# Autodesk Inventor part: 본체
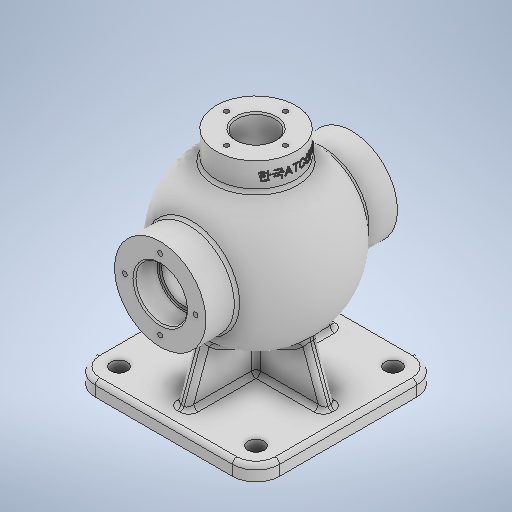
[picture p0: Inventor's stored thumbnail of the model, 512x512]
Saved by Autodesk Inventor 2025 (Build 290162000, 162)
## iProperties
Created: 2024-07
Part Number: 본체
Material: 일반
Document SubType Name: Modeling
Designer: parkm
Density: 1 g/cm^3
Appearance: 기본값
Author: parkm
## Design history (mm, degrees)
sketch "스케치1"
  geometry: L1 (62.5, 62.5)-(-62.5, 62.5); L2 (-62.5, 62.5)-(-62.5, -62.5); L3 (-62.5, -62.5)-(62.5, -62.5); L4 (62.5, -62.5)-(62.5, 62.5); L5 (62.5, 62.5)-(-62.5, -62.5); L6 (-62.5, 62.5)-(62.5, -62.5); 1 further point
  constraints: 12 end point, 2 midpoint, 2 parallel, 1 horizontal, 1 perpendicular
  dimensions: "d0" = 125 distance of L2.end L3.end; "d1" = 125 distance of L1.end L2.end
extrude "돌출1" new body sketch "스케치1" distance "d2" = 10; taper "d3" = 0 deg
fillet "모깎기1" dims "d4" = 16
sketch "스케치2"
  geometry: L1 (-46.5, 0)-(46.5, 0) reference; L2 (0, 144.733)-(0, 0); A1 r 54 centre (0, 85) between (0, 31) and (0, 139); 2 further points
  constraints: 2 end point, 2 midpoint, 2 point on circle, 2 point on line, 1 centre point, 1 vertical, 1 vertical alignment
  dimensions: "d5" = 108 diameter of A1; "d6" = 85 distance of L2.end A1.centre
revolve "회전1" sketch "스케치2" stored, may be unused: angle "d7" = 90 deg
sketch "스케치3"
  geometry: L1 (50, 35.941)-(10, 50.5); L2 (10, 62.5)-(10, 46.5) reference; L3 (0, 62.5)-(10, 62.5) reference; L4 (0, 0)-(175.833, 0); L5 (50, -35.941)-(10, -50.5); L6 (10, 50.5)-(10, -50.5); L7 (10, -46.5)-(10, 46.5) reference; L8 (10, -62.5)-(0, -62.5) reference; L9 (0, -62.5)-(10, -62.5) reference; A1 r 57.102 centre (94.372, 0) between (50, 35.941) and (71.299, -52.233); 7 further points
  constraints: 8 end point, 2 midpoint, 2 point on circle, 2 point on line, 2 symmetric about line, 1 centre point, 1 collinear, 1 equal length, 1 horizontal, 2 other
  dimensions: "d8" = 12 vertical distance of point (5, 62.5) L1.end; "d9" = 20 deg angle of L1 L3; "d13" = 20 deg angle of L5 L8; "d14" = 40 horizontal distance of L1.start L1.end; "d89" = 12 vertical distance of point (5, -62.5) L5.end (derived)
extrude "돌출2" join sketch "스케치3" stored distance "d11" = 8; taper "d12" = 0 deg
sketch "스케치4"
  geometry: L1 (-30.003, 66.314)-(-50.5, 10); L2 (30.003, 66.314)-(50.5, 10); L3 (-62.5, 10)-(-46.5, 10) reference; L4 (46.5, 10)-(62.5, 10) reference; L5 (-62.5, 0)-(-62.5, 10) reference; L6 (62.5, 10)-(62.5, 0) reference; L7 (-50.5, 10)-(50.5, 10); A1 r 46.287 centre (0, 101.56) between (-30.003, 66.314) and (30.003, 66.314); 3 further points
  constraints: 6 end point, 2 point on circle, 2 point on line, 1 centre point, 1 collinear, 1 equal length
  dimensions: "d15" = 12 distance from line of L1.end L5; "d16" = 12 distance from line of L2.end L6; "d17" = 20 deg angle of L1 L5; "d18" = 20 deg angle of L2 L6
extrude "돌출3" join sketch "스케치4" stored distance "d19" = 8; taper "d20" = 0 deg
fillet "모깎기2" dims "d21" = 3
fillet "모깎기3" dims "d22" = 3
fillet "모깎기4" dims "d23" = 3
fillet "모깎기5" dims "d24" = 3
sketch "스케치5"
  geometry: C1 r 31 at (0, 85); A1 r 54 centre (0, 85) between (38.709, 47.349) and (-38.709, 47.349) reference; 1 further point
  constraints: 1 centre point, 1 concentric
  dimensions: "d25" = 62 diameter of C1
extrude "돌출4" join sketch "스케치5" stored distance "d26" = 130; taper "d27" = 0 deg
fillet "모깎기6" dims "d28" = 3
node "작업 평면1"
sketch "스케치6"
  geometry: C1 r 27 at (0, 0); 1 further point
  constraints: 1 centre point, 1 coincident
  dimensions: "d30" = 54 diameter of C1
extrude "돌출5" join sketch "스케치6" distance "d31" = 30; taper "d32" = 0 deg
fillet "모깎기7" dims "d33" = 3
sketch "스케치8"
  geometry: L1 (0, 0)-(0, 160.102); A1 r 44 centre (0, 85) between (0, 41) and (0, 129); A2 r 54 centre (0, 85) between (38.709, 47.349) and (-38.709, 47.349) reference
  constraints: 2 end point, 2 point on circle, 2 point on line, 1 centre point, 1 concentric, 1 vertical
  dimensions: "d34" = 88 diameter of A1
revolve "회전2" sketch "스케치8" stored, may be unused: angle "d39" = 90 deg
sketch "스케치9"
  geometry: C1 r 31 at (0, 0) reference; C2 r 17.5 at (0, 0); 1 further point
  constraints: 1 centre point, 1 coincident
  dimensions: "d40" = 35 diameter of C2
extrude "돌출6" cut sketch "스케치9" distance "d41" = 16; taper "d42" = 0 deg
sketch "스케치10"
  geometry: C1 r 17.5 at (0, 0) reference; 1 further point
extrude "돌출7" cut sketch "스케치10" distance "d43" = 16; taper "d44" = 0 deg
sketch "스케치11"
  geometry: C1 r 17.5 at (0, 0) reference; C2 r 15 at (0, 0); 1 further point
  constraints: 1 centre point, 1 coincident
  dimensions: "d45" = 30 diameter of C2
extrude "돌출8" cut sketch "스케치11" extent not by distance; stored distance "d46" = 0; taper "d47" = 0 deg
sketch "스케치12"
  geometry: C1 r 13 at (0, 0); 1 further point
  constraints: 1 centre point, 1 coincident
  dimensions: "d48" = 26 diameter of C1
extrude "돌출9" cut sketch "스케치12" stored distance "d49" = 10; taper "d50" = 0 deg
chamfer "모따기1" distance "d51" = 1; stored, may be unused: second distance "d52" = 2, angle "d53" = 45 deg
fillet "모깎기8" dims "d54" = 0.6
sketch "스케치13"
  geometry: L1 (-70.97, 0)-(83.117, 0); L2 (0, 46.873)-(0, -34.996); C1 r 31 at (0, 0) reference; A1 r 24 centre (0, 0) between (0, 24) and (-24, 0); 3 further points
  constraints: 6 point on line, 4 end point, 4 point on circle, 1 centre point, 1 concentric, 1 horizontal, 1 vertical
  dimensions: "d55" = 48 diameter of A1
hole "구멍1" sketch "스케치13" at (0, 24), (-24, 0), (0, -24), (24, 0) diameter "d56" = 3.242; stored, may be unused: countersink angle "d60" = 90 deg, drill point angle "d62" = 120 deg; dims "d57" = 12, "d58" = 4, "d59" = 2, "d61" = 15
sketch "스케치14"
  geometry: C1 r 1.621 at (-24, 0) reference; C2 r 1.621 at (0, 24) reference; C3 r 1.621 at (24, 0) reference; C4 r 1.621 at (0, -24) reference; 1 further point
hole "구멍2" sketch "스케치14" at (0, 24), (-24, 0), (0, -24), (24, 0) diameter "d63" = 3.242; stored, may be unused: countersink angle "d67" = 90 deg, drill point angle "d69" = 120 deg; dims "d64" = 12, "d65" = 4, "d66" = 2, "d68" = 15
sketch "스케치15"
  geometry: L1 (-105.545, 0)-(92.862, 0); L2 (0, 73.134)-(0, -31.988); A1 r 20 centre (0, 0) between (0, 20) and (-20, 0); 3 further points
  constraints: 5 point on line, 4 end point, 4 point on circle, 1 centre point, 1 coincident, 1 horizontal, 1 vertical
  dimensions: "d70" = 40 diameter of A1
hole "구멍3" sketch "스케치15" at (0, 20), (-20, 0), (20, 0), (0, -20) diameter "d71" = 3.242; stored, may be unused: countersink angle "d75" = 90 deg, drill point angle "d77" = 120 deg; dims "d72" = 9, "d73" = 4, "d74" = 2, "d76" = 11
sketch "스케치16"
  geometry: A1 r 13 centre (46.5, -46.5) between (46.5, -59.5) and (59.5, -46.5) reference; A2 r 13 centre (46.5, 46.5) between (59.5, 46.5) and (46.5, 59.5) reference; A3 r 13 centre (-46.5, -46.5) between (-59.5, -46.5) and (-46.5, -59.5) reference; A4 r 13 centre (-46.5, 46.5) between (-46.5, 59.5) and (-59.5, 46.5) reference; 5 further points
  constraints: 4 coincident
hole "구멍4" sketch "스케치16" at (46.5, -46.5), (46.5, 46.5), (-46.5, -46.5), (-46.5, 46.5) diameter "d78" = 11; stored, may be unused: countersink angle "d82" = 90 deg, drill point angle "d84" = 0 deg; dims "d79" = 9, "d80" = 4, "d81" = 2, "d83" = 11
node "작업 평면2"
sketch "스케치17"
  geometry: L1 (150, -27)-(150, 27) reference; L2 (0, 0)-(196.455, 0); 1 further point
  constraints: 2 end point, 1 horizontal, 1 point on line, 1 other
  dimensions: "d86" = 9 distance from line of point (141, 0) L1
feature "엠보싱1" sketch "스케치17" dims "d0" = 125, "d1" = 125, "d87" = 0.5, "d88" = 0
node "솔리드1"
node "투영된 루프1"
feature "A9D066F2-1C7D-4E18-AEED-F7BC21143FA4" dims "d78" = 11, "d79" = 9, "d80" = 4, "d81" = 2, "d82" = 90 deg, "d83" = 11, "d84" = 0
other parameters: "d35" = 0.5, "d36" = 2, "d37" = 0, "d85" = 27
